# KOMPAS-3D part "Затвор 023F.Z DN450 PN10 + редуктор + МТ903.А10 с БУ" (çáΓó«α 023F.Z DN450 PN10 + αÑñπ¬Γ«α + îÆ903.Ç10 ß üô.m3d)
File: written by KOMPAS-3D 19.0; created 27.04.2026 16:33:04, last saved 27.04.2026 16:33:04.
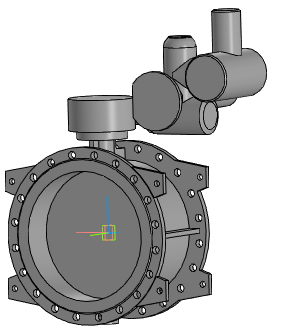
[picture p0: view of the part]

Document properties: Полное имя файла: ..\..\Затвор 023F.Z DN400-DN1600 + редуктор + МТ903\Затвор 023F.Z DN450 PN10 + редуктор + МТ903.А10 с БУ.a3d

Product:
- Part/product: Затвор 023F.Z DN450 PN10 + редуктор + МТ903.А10 с БУ
    Масса: 350.334

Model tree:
1. Операция без истории:1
